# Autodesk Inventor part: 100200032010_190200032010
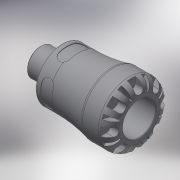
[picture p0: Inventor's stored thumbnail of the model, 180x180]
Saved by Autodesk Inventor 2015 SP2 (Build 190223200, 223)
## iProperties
Created: 2016-12
Part Number: 100200032010_190200032010
Material: Generic
Description: PLASSON MALE ADAPTOR 32X1" SERIES 1
Document SubType Name: Modeling
Designer: KIM
Mass: 447.839 g
Surface Area: 722.341 cm^2
Volume: 447.839 cm^3
Density: 1 g/cm^3
Appearance: Default
Author: KIM
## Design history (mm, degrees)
derived "1002.ipt"
feature "Solid1::1002.ipt"
tag "TaggingFeature1"
body "Solid1"
other parameters: "d0" = 84, "d1" = 23.1, "d2" = 32, "d4" = 58, "d6" = 55, "d8" = 49.3, "d13" = 7.2, "d14" = 7.2, "d15" = 0, "d17" = 360 deg, "d19" = 8 deg, "d20" = 0.64, "d21" = 0.64, "d22" = 8 deg, "d24" = 0, "d26" = 360 deg, "d32" = 0.925, "d33" = 5.8, "d34" = 33.249, "d35" = 4, "d38" = 19, "d39" = 0.99747, "d42" = 11.2, "d43" = 7.36, "d45" = 14.112, "d46" = 0, "d59" = 360 deg, "d61" = 9.52, "d62" = 0.64, "d64" = 0, "d65" = 0.58, "d_" = 32, "E_" = 58, "H_" = 84, "l_" = 55, "R_" = 33.249, "l_2" = 19, "d9" = 9, "d11" = 58
